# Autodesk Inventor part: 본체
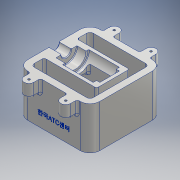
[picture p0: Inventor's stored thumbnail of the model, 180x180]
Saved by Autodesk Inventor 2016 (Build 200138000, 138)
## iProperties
Created: 2018-01
Part Number: 본체
Material: 알루미늄 6061
Document SubType Name: Modeling
Designer: USER
Density: 2.7 g/cm^3
Appearance: 알루미늄 - 평지
Mass: 995.217 g
Surface Area: 834.406 cm^2
Volume: 368.599 cm^3
Author: USER
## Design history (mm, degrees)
sketch "스케치1"
  geometry: L1 (-55, -55)-(55, -55); L2 (55, -55)-(55, 55); L3 (55, 55)-(-55, 55); L4 (-55, 55)-(-55, -55); L5 (-55, -55)-(55, 55); L6 (55, -55)-(-55, 55); 1 further point
  constraints: 12 end point, 2 midpoint, 2 parallel, 1 horizontal, 1 perpendicular
  dimensions: "d0" = 110 distance of L2.end L3.end; "d1" = 110 distance of L1.end L2.end
extrude "돌출1" new body sketch "스케치1" distance "d2" = 65; taper "d3" = 0 deg
sketch "스케치2"
  geometry: L1 (-55, 55)-(-55, -55) reference; L2 (55, 55)-(-55, 55) reference; L3 (-55, -55)-(55, -55) reference; L4 (-35.5, 65)-(-35.5, 55); L5 (-20.5, 65)-(-20.5, 55); L6 (20.5, 65)-(20.5, 55); L7 (35.5, 65)-(35.5, 55); L8 (20.5, -65)-(20.5, -55); L9 (-20.5, -65)-(-20.5, -55); L10 (-35.5, -65)-(-35.5, -55); L11 (35.5, -65)-(35.5, -55); L12 (-35.5, 55)-(-20.5, 55); L13 (20.5, 55)-(35.5, 55); L14 (35.5, -55)-(20.5, -55); L15 (-20.5, -55)-(-35.5, -55); A1 r 7.5 centre (-28, 65) between (-20.5, 65) and (-35.5, 65); A2 r 7.5 centre (28, 65) between (35.5, 65) and (20.5, 65); A3 r 7.5 centre (28, -65) between (20.5, -65) and (35.5, -65); A4 r 7.5 centre (-28, -65) between (-35.5, -65) and (-20.5, -65); 1 further point
  constraints: 24 end point, 8 point on circle, 8 point on line, 8 tangent, 7 perpendicular, 4 centre point, 3 collinear, 2 horizontal alignment, 2 vertical alignment, 1 horizontal, 1 vertical
  dimensions: "d4" = 15 diameter of A2; "d5" = 15 diameter of A1 (= d4); "d6" = 15 diameter of A4 (= d4); "d7" = 15 diameter of A3 (= d4); "d8" = 27 distance from line of A1.centre L1; "d9" = 56 distance of A2.centre A1.centre; "d10" = 10 distance from line of A1.centre L2; "d11" = 10 distance from line of A4.centre L3
extrude "돌출2" join sketch "스케치2" distance "d12" = 20; taper "d13" = 0 deg
sketch "스케치3"
  geometry: L1 (-45, 45)-(45, 45); L2 (45, 45)-(45, -45); L3 (45, -45)-(-45, -45); L4 (-45, -45)-(-45, -25); L5 (-45, -25)-(35, -25); L6 (35, -25)-(35, 25); L7 (35, 25)-(-45, 25); L8 (-45, 25)-(-45, 45); L9 (20.5, 55)-(-20.5, 55) reference; L10 (-55, 55)-(-55, -55) reference; L11 (55, -55)-(55, 55) reference; L12 (-20.5, -55)-(20.5, -55) reference; 1 further point
  constraints: 16 end point, 7 perpendicular, 1 horizontal, 1 point on line
  dimensions: "d14" = 30 distance between parallel lines of L7 L9; "d15" = 20 distance between parallel lines of L1 L7; "d16" = 10 distance between parallel lines of L8 L10; "d17" = 10 distance between parallel lines of L11 L2; "d18" = 10 distance between parallel lines of L12 L3; "d19" = 20 distance between parallel lines of L3 L5; "d23" = 20 distance between parallel lines of L11 L6
extrude "돌출3" cut sketch "스케치3" stored distance "d21" = 20; taper "d22" = 0 deg
sketch "스케치4"
  geometry: L1 (45, 8.564)-(45, 0); L2 (45, 0)-(-35, 0); L3 (-55, 0)-(55, 0) reference; L4 (45, 8.564)-(-35, 30); L5 (-35, 65)-(-35, 0) reference; L6 (-35, 30)-(-35, 0); L7 (55, 0)-(55, 65) reference; 1 further point
  constraints: 8 end point, 1 collinear, 1 perpendicular, 1 point on line, 1 vertical alignment
  dimensions: "d24" = 30 distance from line of L3 L4.end; "d25" = 105 deg angle of L4 L1; "d26" = 10 distance between parallel lines of L1 L7
extrude "돌출4" cut sketch "스케치4" stored distance "d27" = 55; taper "d28" = 0 deg
sketch "스케치5"
  geometry: L1 (-35, 30)-(45, 8.564) reference; L2 (-20, 31.157)-(55, 11.061); L3 (55, 0)-(55, 65) reference; L4 (55, 11.061)-(55, 29.061); L5 (55, 29.061)-(17, 39.243); L6 (17, 39.243)-(17, 61.157); L7 (17, 61.157)-(-20, 61.157); L8 (-20, 61.157)-(-20, 31.157); 1 further point
  constraints: 12 end point, 2 parallel, 2 perpendicular, 2 point on line
  dimensions: "d29" = 5 distance between parallel lines of L1 L2; "d30" = 18 distance of L2.end L4.end; "d31" = 37 distance of L6.end L7.end; "d32" = 75 deg angle of L5 L3; "d33" = 38 distance between parallel lines of L6 L3; "d34" = 30 distance of L7.end L2.start
extrude "돌출5" cut sketch "스케치5" stored distance "d35" = 30; taper "d36" = 0 deg
sketch "스케치6"
  geometry: L1 (35.5, 65)-(55, 65) reference; L2 (55, 65)-(101.354, 65); L3 (55, 0)-(55, 65) reference; L4 (55, 65)-(55, 57.5); L5 (55, 57.5)-(36, 57.5); L6 (36, 57.5)-(36, 49); L7 (36, 49)-(22, 49); L8 (22, 49)-(22, 45); L9 (35.5, 45)-(20.5, 45) reference; L10 (22, 45)-(-25, 45); L11 (-25, 45)-(-25, 50); L12 (-25, 50)-(-30, 50); L13 (-20.5, 65)-(-35.5, 65) reference; L14 (-30, 50)-(-30, 65); L15 (-30, 65)-(55, 65); 1 further point
  constraints: 22 end point, 6 perpendicular, 2 horizontal, 2 point on line, 1 collinear, 1 vertical
  dimensions: "d37" = 15 diameter of L5 L2; "d38" = 32 diameter of L7 L2; "d39" = 40 diameter of L10 L2; "d40" = 30 diameter of L12 L2; "d41" = 19 distance of L4.end L5.end; "d42" = 14 distance of L6.end L7.end; "d43" = 47 distance of L8.end L10.end; "d44" = 5 distance of L11.end L12.end
revolve "회전1" sketch "스케치6" stored, may be unused: angle "d45" = 90 deg
sketch "스케치7"
  geometry: L1 (0, 0)-(0, 65) reference; L2 (0, 0)-(110, 0) reference; 2 further points
  constraints: 1 other
  dimensions: "d46" = 55 distance from line of point (55, 20) L1; "d47" = 20 distance from line of L2 point (55, 20)
feature "엠보싱1" sketch "스케치7" dims "d0" = 110, "d1" = 110, "d48" = 0.5, "d49" = 0
fillet "모깎기1" dims "d50" = 1
chamfer "모따기1" distance "d51" = 1; stored, may be unused: second distance "d52" = 2, angle "d53" = 45 deg
fillet "모깎기2" dims "d54" = 15
fillet "모깎기3" dims "d55" = 5
fillet "모깎기4" dims "d56" = 3
fillet "모깎기5" dims "d57" = 3
fillet "모깎기6" dims "d58" = 3
fillet "모깎기7" dims "d59" = 3
sketch "스케치8"
  geometry: A1 r 7.5 centre (-28, 65) between (-20.5, 65) and (-35.5, 65) reference; A2 r 7.5 centre (28, 65) between (35.5, 65) and (20.5, 65) reference; A3 r 7.5 centre (28, -65) between (20.5, -65) and (35.5, -65) reference; A4 r 7.5 centre (-28, -65) between (-35.5, -65) and (-20.5, -65) reference; 5 further points
  constraints: 4 coincident
hole "구멍1" sketch "스케치8" at (-28, 65), (28, 65), (28, -65), (-28, -65) diameter "d60" = 3.242; stored, may be unused: countersink angle "d64" = 90 deg, drill point angle "d66" = 118 deg; dims "d61" = 9, "d62" = 4, "d63" = 2, "d65" = 11
fillet "모깎기11" dims "d70" = 3
node "솔리드1"
